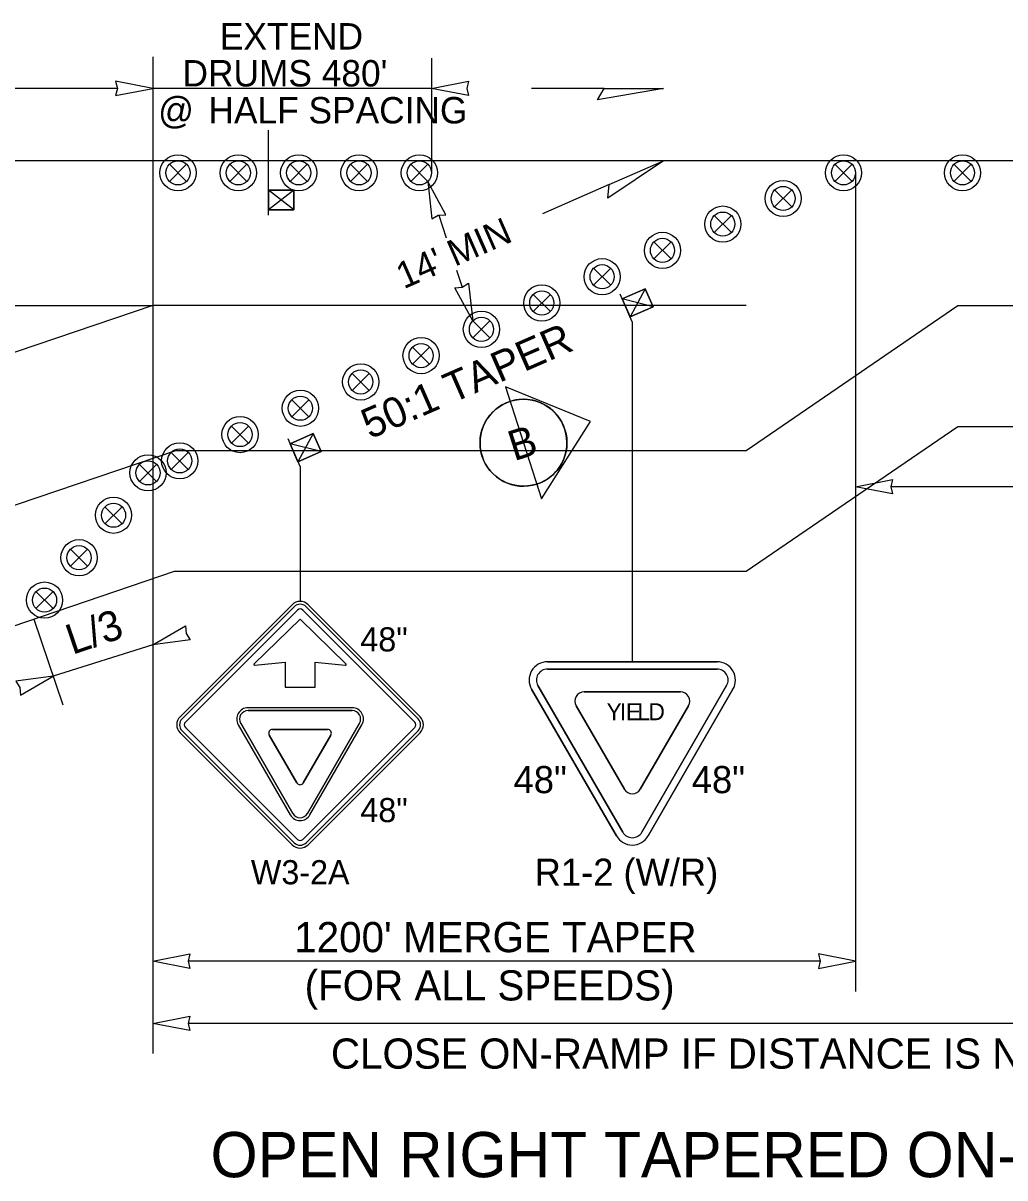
# Model space of a CAD drawing. Extents: x 99999 to 100116, y 99995 to 100013.
# Drawn here: x 100070.259 to 100072.862, y 100004.799 to 100007.86 of the extents above; entities that cross this region are included whole.
import ezdxf

# ---------------------------------------------------------------- set-up
doc = ezdxf.new("R2010")
doc.units = 0
for name, color, linetype in [('RD_MK_LineEdgeYellow', 7, 'Continuous'), ('RD_MK_LineLane', 7, 'Continuous'), ('SH_DE_DetailHeading2Text', 7, 'Continuous'), ('SH_GI_SectionCut', 7, 'Continuous'), ('TR_SN_ConstructionSigns', 7, 'Continuous'), ('TR_WZ_PortableSignMount5ftMinBlk-Org', 7, 'Continuous'), ('TR_WZ_PortableSignMount5ftMinRed-Wht', 7, 'Continuous'), ('TR_WZ_TrafficSafetyDrum', 7, 'Continuous'), ('TR_WZ_WorkZoneDetails', 7, 'Continuous'), ('TR_WZ_WorkZoneTextCurrent', 7, 'Continuous')]:
    doc.layers.add(name, color=color, linetype=linetype)

msp = doc.modelspace()

# ---------------------------------------------------------------- linework, layer by layer
at = {"layer": 'RD_MK_LineEdgeYellow'}
for p, q in [((100072.1758, 100006.7269), (100072.7368, 100007.1109)), ((100072.7368, 100007.1109), (100075.43, 100007.1109)), ((100070.6655, 100006.7269), (100068.195, 100005.8927)), ((100070.6655, 100006.7269), (100072.1758, 100006.7269))]:
    msp.add_line(p, q, dxfattribs=at)
at = {"layer": 'RD_MK_LineLane'}
for points in [[(100075.43, 100007.4949), (100068.195, 100007.4949)], [(100072.1758, 100007.1109), (100070.6024, 100007.1109)]]:
    msp.add_lwpolyline(points, dxfattribs=at)
at = {"layer": 'SH_GI_SectionCut'}
for p, q in [((100071.5379, 100006.8959), (100071.5503, 100006.8571)), ((100071.7627, 100006.8041), (100071.5379, 100006.8959)), ((100071.5379, 100006.8959), (100071.6329, 100006.5989)), ((100071.6329, 100006.5989), (100071.7627, 100006.8041)), ((100071.6205, 100006.6377), (100071.6329, 100006.5989))]:
    msp.add_line(p, q, dxfattribs=at)
msp.add_circle((100071.5854, 100006.7474), 0.1152, dxfattribs=at)
for start, end in [(17.7228, 287.7205), (287.7205, 107.725), (287.7205, 17.7228)]:
    msp.add_arc((100071.5854, 100006.7474), 0.1152, start, end, dxfattribs=at)
at = {"layer": 'TR_SN_ConstructionSigns'}
for p, q in [((100070.9719, 100006.3181), (100070.6749, 100006.0211)), ((100070.9772, 100006.3128), (100070.6802, 100006.0158)), ((100070.689, 100006.007), (100070.986, 100006.304)), ((100071.0002, 100006.304), (100071.2971, 100006.007)), ((100071.306, 100006.0158), (100071.009, 100006.3128)), ((100071.3113, 100006.0211), (100071.0143, 100006.3181)), ((100070.9931, 100006.2799), (100070.8713, 100006.1617)), ((100071.1148, 100006.1617), (100070.9931, 100006.2799)), ((100070.8733, 100006.1574), (100070.9531, 100006.1658)), ((100070.9531, 100006.1658), (100070.9531, 100006.0999)), ((100071.0331, 100006.0999), (100071.0331, 100006.1658)), ((100071.0331, 100006.1658), (100071.1128, 100006.1574)), ((100072.0987, 100006.1669), (100071.6491, 100006.1669)), ((100071.6491, 100006.1475), (100071.6491, 100006.1476)), ((100071.6491, 100006.1476), (100071.8739, 100006.1476)), ((100071.8739, 100006.1476), (100071.6491, 100006.1476)), ((100071.6491, 100006.1476), (100071.6491, 100006.1475)), ((100070.9531, 100006.0999), (100071.0331, 100006.0999)), ((100071.8317, 100005.7052), (100071.6069, 100006.0939)), ((100071.6069, 100006.0939), (100071.8317, 100005.7052)), ((100071.8486, 100005.715), (100071.6238, 100006.1036)), ((100071.6238, 100006.1036), (100071.8486, 100005.715)), ((100071.8739, 100006.0867), (100071.7461, 100006.0867)), ((100071.7461, 100006.0867), (100071.8739, 100006.0867)), ((100072.0017, 100006.0867), (100071.8739, 100006.0867)), ((100071.8739, 100006.0867), (100072.0017, 100006.0867)), ((100072.124, 100006.1036), (100071.8992, 100005.715)), ((100071.8992, 100005.715), (100072.124, 100006.1036)), ((100072.1408, 100006.0939), (100071.916, 100005.7052)), ((100071.916, 100005.7052), (100072.1408, 100006.0939)), ((100071.1311, 100006.0449), (100070.855, 100006.0449)), ((100070.855, 100006.0374), (100071.1311, 100006.0374)), ((100071.1311, 100006.0374), (100070.855, 100006.0374)), ((100071.725, 100006.0502), (100071.8528, 100005.8293)), ((100071.8528, 100005.8293), (100071.725, 100006.0502)), ((100071.895, 100005.8293), (100072.0228, 100006.0502)), ((100072.0228, 100006.0502), (100071.895, 100005.8293)), ((100070.986, 100005.6959), (100070.689, 100005.9929)), ((100070.8291, 100005.9999), (100070.9671, 100005.7608)), ((100070.9736, 100005.7646), (100070.8356, 100006.0037)), ((100070.8356, 100006.0037), (100070.9736, 100005.7646)), ((100071.2971, 100005.9929), (100071.0002, 100005.6959)), ((100071.1506, 100006.0037), (100071.0126, 100005.7646)), ((100071.0126, 100005.7646), (100071.1506, 100006.0037)), ((100071.0191, 100005.7608), (100071.1571, 100005.9999)), ((100070.6749, 100005.9787), (100070.9719, 100005.6817)), ((100070.6802, 100005.984), (100070.9772, 100005.687)), ((100070.9113, 100005.9724), (100070.9844, 100005.8458)), ((100070.9844, 100005.8458), (100070.9113, 100005.9724)), ((100071.0662, 100005.9874), (100070.92, 100005.9874)), ((100070.92, 100005.9874), (100071.0662, 100005.9874)), ((100071.0017, 100005.8458), (100071.0748, 100005.9724)), ((100071.0748, 100005.9724), (100071.0017, 100005.8458)), ((100071.009, 100005.687), (100071.306, 100005.984)), ((100071.0143, 100005.6817), (100071.3113, 100005.9787))]:
    msp.add_line(p, q, dxfattribs=at)
for points in [[(100071.6491, 100006.1669), (100072.0987, 100006.1669)], [(100071.8739, 100006.1476), (100072.0987, 100006.1476), (100072.0987, 100006.1475)], [(100072.0987, 100006.1475), (100072.0987, 100006.1476), (100071.8739, 100006.1476)]]:
    msp.add_lwpolyline(points, dxfattribs=at)
for centre, radius, start, end in [((100070.9931, 100006.2969), 0.03, 45, 135), ((100070.9931, 100006.2969), 0.0225, 45, 135), ((100070.9931, 100006.2969), 0.01, 45, 135), ((100070.8731, 100006.1599), 0.0025, 134.1559, 275.9533), ((100071.1131, 100006.1599), 0.0025, 264.0467, 45.8441), ((100071.6491, 100006.1182), 0.0487, 90, 210.0517), ((100071.6491, 100006.1182), 0.0487, 90, 210.0517), ((100071.6491, 100006.1182), 0.0292, 90, 210.0517), ((100071.6491, 100006.1182), 0.0292, 90, 210.0517), ((100072.0987, 100006.1182), 0.0487, 329.9522, 90), ((100072.0987, 100006.1182), 0.0487, 329.9522, 90), ((100072.0987, 100006.1182), 0.0292, 329.9522, 90), ((100072.0987, 100006.1182), 0.0292, 329.9522, 90), ((100071.7461, 100006.0624), 0.0244, 90, 210.0513), ((100071.7461, 100006.0624), 0.0244, 90, 210.0513), ((100072.0017, 100006.0624), 0.0244, 329.9514, 90), ((100072.0017, 100006.0624), 0.0244, 329.9514, 90), ((100070.6961, 100005.9999), 0.03, 135, 225), ((100070.855, 100006.0149), 0.03, 90, 210), ((100070.855, 100006.0149), 0.0225, 90, 210), ((100070.855, 100006.0149), 0.0225, 90, 210), ((100071.1311, 100006.0149), 0.03, 330, 90), ((100071.1311, 100006.0149), 0.0225, 330, 90), ((100071.1311, 100006.0149), 0.0225, 330, 90), ((100071.2901, 100005.9999), 0.03, 315, 45), ((100070.6961, 100005.9999), 0.0225, 135, 225), ((100070.6961, 100005.9999), 0.01, 135, 225), ((100071.2901, 100005.9999), 0.01, 315, 45), ((100071.2901, 100005.9999), 0.0225, 315, 45), ((100070.92, 100005.9774), 0.01, 90, 210), ((100070.92, 100005.9774), 0.01, 90, 210), ((100071.0662, 100005.9774), 0.01, 330, 90), ((100071.0662, 100005.9774), 0.01, 330, 90), ((100070.9931, 100005.8508), 0.01, 210, 330), ((100070.9931, 100005.8508), 0.01, 210, 330), ((100071.8739, 100005.8415), 0.0244, 210.0519, 329.9525), ((100071.8739, 100005.8415), 0.0244, 210.0519, 329.9525), ((100070.9931, 100005.7758), 0.03, 210, 330), ((100070.9931, 100005.7758), 0.0225, 210, 330), ((100070.9931, 100005.7758), 0.0225, 210, 330), ((100071.8739, 100005.7296), 0.0292, 210.0518, 329.9516), ((100071.8739, 100005.7296), 0.0292, 210.0518, 329.9516), ((100070.9931, 100005.7029), 0.0225, 225, 315), ((100070.9931, 100005.7029), 0.01, 225, 315), ((100071.8739, 100005.7296), 0.0487, 210.0518, 329.9516), ((100071.8739, 100005.7296), 0.0487, 210.0518, 329.9516), ((100070.9931, 100005.7029), 0.03, 225, 315)]:
    msp.add_arc(centre, radius, start, end, dxfattribs=at)
at = {"layer": 'TR_WZ_PortableSignMount5ftMinBlk-Org'}
for p, q in [((100070.9094, 100007.3509), (100070.9094, 100007.4309)), ((100070.9761, 100007.4169), (100070.9094, 100007.3649)), ((100070.9761, 100007.3649), (100070.9094, 100007.4169)), ((100070.9427, 100007.3909), (100070.9427, 100007.3909)), ((100070.9428, 100007.391), (100070.9428, 100007.391)), ((100070.9931, 100006.6844), (100070.9611, 100006.7577)), ((100071.0279, 100006.7715), (100070.9875, 100006.6972)), ((100071.0486, 100006.7239), (100070.9667, 100006.7449)), ((100071.0077, 100006.7344), (100071.0077, 100006.7344)), ((100071.0078, 100006.7345), (100071.0078, 100006.7345))]:
    msp.add_line(p, q, dxfattribs=at)
for points in [[(100070.9761, 100007.4169), (100070.9761, 100007.3649), (100070.9094, 100007.3649), (100070.9094, 100007.4169)], [(100070.9094, 100007.3649), (100070.9761, 100007.3649), (100070.9761, 100007.4169), (100070.9094, 100007.4169)], [(100071.0279, 100006.7715), (100071.0486, 100006.7239), (100070.9875, 100006.6972), (100070.9667, 100006.7449)], [(100070.9875, 100006.6972), (100071.0486, 100006.7239), (100071.0279, 100006.7715), (100070.9667, 100006.7449)]]:
    msp.add_lwpolyline(points, close=True, dxfattribs=at)
at = {"layer": 'TR_WZ_PortableSignMount5ftMinRed-Wht'}
for p, q in [((100071.9084, 100007.1554), (100071.868, 100007.0811)), ((100071.8736, 100007.0683), (100071.8416, 100007.1416)), ((100071.9291, 100007.1078), (100071.8472, 100007.1288)), ((100071.8882, 100007.1184), (100071.8882, 100007.1184)), ((100071.8882, 100007.1183), (100071.8882, 100007.1183))]:
    msp.add_line(p, q, dxfattribs=at)
for points in [[(100071.9084, 100007.1554), (100071.9291, 100007.1078), (100071.868, 100007.0811), (100071.8472, 100007.1288)], [(100071.868, 100007.0811), (100071.9291, 100007.1078), (100071.9084, 100007.1554), (100071.8472, 100007.1288)]]:
    msp.add_lwpolyline(points, close=True, dxfattribs=at)
at = {"layer": 'TR_WZ_TrafficSafetyDrum'}
for p, q in [((100070.6468, 100007.4855), (100070.692, 100007.4403)), ((100070.692, 100007.4855), (100070.6468, 100007.4403)), ((100070.8068, 100007.4855), (100070.852, 100007.4403)), ((100070.852, 100007.4855), (100070.8068, 100007.4403)), ((100070.9668, 100007.4855), (100071.012, 100007.4403)), ((100071.012, 100007.4855), (100070.9668, 100007.4403)), ((100071.1268, 100007.4855), (100071.172, 100007.4403)), ((100071.172, 100007.4855), (100071.1268, 100007.4403)), ((100071.2868, 100007.4855), (100071.332, 100007.4403)), ((100071.332, 100007.4855), (100071.2868, 100007.4403)), ((100072.4113, 100007.4855), (100072.4566, 100007.4403)), ((100072.4566, 100007.4855), (100072.4113, 100007.4403)), ((100072.7268, 100007.4855), (100072.772, 100007.4403)), ((100072.772, 100007.4855), (100072.7268, 100007.4403)), ((100072.2513, 100007.4176), (100072.2966, 100007.3724)), ((100072.2966, 100007.4176), (100072.2513, 100007.3724)), ((100072.0913, 100007.3497), (100072.1366, 100007.3045)), ((100072.1366, 100007.3497), (100072.0913, 100007.3045)), ((100071.9313, 100007.28), (100071.9766, 100007.2347)), ((100071.9766, 100007.28), (100071.9313, 100007.2347)), ((100071.7713, 100007.2102), (100071.8166, 100007.165)), ((100071.8166, 100007.2102), (100071.7713, 100007.165)), ((100071.6113, 100007.1405), (100071.6566, 100007.0952)), ((100071.6566, 100007.1405), (100071.6113, 100007.0952)), ((100071.4513, 100007.0708), (100071.4966, 100007.0255)), ((100071.4966, 100007.0708), (100071.4513, 100007.0255)), ((100071.2913, 100007.001), (100071.3366, 100006.9558)), ((100071.3366, 100007.001), (100071.2913, 100006.9558)), ((100071.1313, 100006.9313), (100071.1766, 100006.886)), ((100071.1766, 100006.9313), (100071.1313, 100006.886)), ((100070.9713, 100006.8615), (100071.0166, 100006.8163)), ((100071.0166, 100006.8615), (100070.9713, 100006.8163)), ((100070.8113, 100006.7918), (100070.8566, 100006.7465)), ((100070.8566, 100006.7918), (100070.8113, 100006.7465)), ((100070.6513, 100006.722), (100070.6966, 100006.6768)), ((100070.6966, 100006.722), (100070.6513, 100006.6768)), ((100070.5673, 100006.6902), (100070.6125, 100006.645)), ((100070.6125, 100006.6902), (100070.5673, 100006.645)), ((100070.4758, 100006.5778), (100070.5211, 100006.5325)), ((100070.5211, 100006.5778), (100070.4758, 100006.5325)), ((100070.3844, 100006.4653), (100070.4296, 100006.4201)), ((100070.4296, 100006.4653), (100070.3844, 100006.4201)), ((100070.2929, 100006.3529), (100070.3382, 100006.3076)), ((100070.3382, 100006.3529), (100070.2929, 100006.3076))]:
    msp.add_line(p, q, dxfattribs=at)
for centre, radius in [((100070.6694, 100007.4629), 0.048), ((100070.6694, 100007.4629), 0.048), ((100070.6694, 100007.4629), 0.032), ((100070.8294, 100007.4629), 0.048), ((100070.8294, 100007.4629), 0.048), ((100070.8294, 100007.4629), 0.032), ((100070.9894, 100007.4629), 0.048), ((100070.9894, 100007.4629), 0.048), ((100070.9894, 100007.4629), 0.032), ((100071.1494, 100007.4629), 0.048), ((100071.1494, 100007.4629), 0.048), ((100071.1494, 100007.4629), 0.032), ((100071.3094, 100007.4629), 0.048), ((100071.3094, 100007.4629), 0.048), ((100071.3094, 100007.4629), 0.032), ((100072.4339, 100007.4629), 0.048), ((100072.4339, 100007.4629), 0.048), ((100072.4339, 100007.4629), 0.032), ((100072.7494, 100007.4629), 0.048), ((100072.7494, 100007.4629), 0.048), ((100072.7494, 100007.4629), 0.032), ((100072.2739, 100007.395), 0.048), ((100072.2739, 100007.395), 0.048), ((100072.2739, 100007.395), 0.032), ((100072.1139, 100007.3271), 0.048), ((100072.1139, 100007.3271), 0.048), ((100072.1139, 100007.3271), 0.032), ((100071.9539, 100007.2574), 0.048), ((100071.9539, 100007.2574), 0.048), ((100071.9539, 100007.2574), 0.032), ((100071.7939, 100007.1876), 0.048), ((100071.7939, 100007.1876), 0.048), ((100071.7939, 100007.1876), 0.032), ((100071.6339, 100007.1179), 0.048), ((100071.6339, 100007.1179), 0.048), ((100071.6339, 100007.1179), 0.032), ((100071.4739, 100007.0481), 0.048), ((100071.4739, 100007.0481), 0.048), ((100071.4739, 100007.0481), 0.032), ((100071.3139, 100006.9784), 0.048), ((100071.3139, 100006.9784), 0.048), ((100071.3139, 100006.9784), 0.032), ((100071.1539, 100006.9086), 0.048), ((100071.1539, 100006.9086), 0.048), ((100071.1539, 100006.9086), 0.032), ((100070.9939, 100006.8389), 0.048), ((100070.9939, 100006.8389), 0.048), ((100070.9939, 100006.8389), 0.032), ((100070.8339, 100006.7691), 0.048), ((100070.8339, 100006.7691), 0.048), ((100070.8339, 100006.7691), 0.032), ((100070.6739, 100006.6994), 0.048), ((100070.6739, 100006.6994), 0.048), ((100070.6739, 100006.6994), 0.032), ((100070.5899, 100006.6676), 0.048), ((100070.5899, 100006.6676), 0.048), ((100070.5899, 100006.6676), 0.032), ((100070.4985, 100006.5552), 0.048), ((100070.4985, 100006.5552), 0.048), ((100070.4985, 100006.5552), 0.032), ((100070.407, 100006.4427), 0.048), ((100070.407, 100006.4427), 0.048), ((100070.407, 100006.4427), 0.032), ((100070.3156, 100006.3303), 0.048), ((100070.3156, 100006.3303), 0.048), ((100070.3156, 100006.3303), 0.032)]:
    msp.add_circle(centre, radius, dxfattribs=at)
at = {"layer": 'TR_WZ_WorkZoneDetails'}
for p, q in [((100070.6024, 100007.7703), (100070.6024, 100005.1282)), ((100071.3414, 100007.7669), (100071.3414, 100007.4629)), ((100070.5087, 100007.6869), (100068.2887, 100007.6869)), ((100071.3414, 100007.6869), (100070.6024, 100007.6869)), ((100071.7994, 100007.6869), (100071.6065, 100007.6869)), ((100070.9094, 100007.4309), (100070.9094, 100007.5759)), ((100072.4659, 100007.4629), (100072.4659, 100005.2929)), ((100071.8126, 100007.4317), (100071.6361, 100007.354)), ((100071.3609, 100007.3508), (100071.3803, 100007.2908)), ((100071.408, 100007.2047), (100071.4225, 100007.1599)), ((100069.2533, 100007.1109), (100070.6024, 100007.1109)), ((100070.6024, 100007.1109), (100069.2943, 100006.6692)), ((100071.8736, 100007.0683), (100071.8739, 100006.1669)), ((100072.1758, 100006.4069), (100072.7368, 100006.7909)), ((100072.7368, 100006.7909), (100075.43, 100006.7909)), ((100070.9931, 100006.6844), (100070.9931, 100006.3269)), ((100073.599, 100006.6309), (100072.5596, 100006.6309)), ((100068.195, 100005.5689), (100070.6601, 100006.4069)), ((100070.6601, 100006.4069), (100072.1758, 100006.4069)), ((100070.2871, 100006.2801), (100070.3643, 100006.0529)), ((100070.6024, 100006.2119), (100070.3386, 100006.1286)), ((100072.3722, 100005.3729), (100070.6962, 100005.3729)), ((100074.3691, 100005.2082), (100070.6962, 100005.2082))]:
    msp.add_line(p, q, dxfattribs=at)
for points in [[(100070.6024, 100007.6869), (100070.5041, 100007.7062), (100070.5087, 100007.6869), (100070.5041, 100007.6676)], [(100071.3414, 100007.6869), (100071.4396, 100007.7062), (100071.4351, 100007.6869), (100071.4396, 100007.6676)], [(100071.9566, 100007.6869), (100071.7815, 100007.6561), (100071.7994, 100007.6869)], [(100071.9566, 100007.4949), (100071.8087, 100007.3962), (100071.8126, 100007.4317)], [(100071.332, 100007.4403), (100071.3424, 100007.3407), (100071.3595, 100007.3507), (100071.3792, 100007.352)], [(100071.4513, 100007.0708), (100071.403, 100007.1585), (100071.4227, 100007.16), (100071.4397, 100007.1702)], [(100072.4659, 100006.6309), (100072.5642, 100006.6502), (100072.5596, 100006.6309), (100072.5642, 100006.6116)], [(100070.6024, 100006.2119), (100070.6893, 100006.2618), (100070.6912, 100006.2421), (100070.7017, 100006.2253)], [(100070.3386, 100006.1286), (100070.2393, 100006.1152), (100070.2498, 100006.0985), (100070.2517, 100006.0787)], [(100070.6024, 100005.3729), (100070.7007, 100005.3922), (100070.6962, 100005.3729), (100070.7007, 100005.3537)], [(100072.4659, 100005.3729), (100072.3676, 100005.3922), (100072.3722, 100005.3729), (100072.3676, 100005.3537)], [(100070.6024, 100005.2082), (100070.7007, 100005.2275), (100070.6962, 100005.2082), (100070.7007, 100005.1889)]]:
    msp.add_lwpolyline(points, close=True, dxfattribs=at)

# ---------------------------------------------------------------- texts
at = {"layer": 'SH_DE_DetailHeading2Text'}
msp.add_text('OPEN RIGHT TAPERED ON-RAMP DETAIL', height=0.12, rotation=360, dxfattribs=at).set_placement((100070.7557, 100004.8003))
at = {"layer": 'SH_GI_SectionCut'}
msp.add_text('B', height=0.08, rotation=17.7128, dxfattribs=at).set_placement((100071.5605, 100006.6982))
at = {"layer": 'TR_SN_ConstructionSigns'}
for s, height, p in [('48"', 0.064, (100071.1529, 100006.1942)), ('48"', 0.072, (100072.0316, 100005.8185)), ('48"', 0.064, (100071.1529, 100005.7416)), ('W3-2A', 0.064, (100070.8627, 100005.5769)), ('R1-2 (W/R)', 0.072, (100071.6151, 100005.5729))]:
    msp.add_text(s, height=height, rotation=360, dxfattribs=at).set_placement(p)
for s, height, p in [('Y', 0.045, (100071.8057, 100006.0119)), ('I', 0.045, (100071.8408, 100006.0119)), ('E', 0.045, (100071.857, 100006.0119)), ('L', 0.045, (100071.8876, 100006.0119)), ('D', 0.045, (100071.9168, 100006.0119)), ('48"', 0.072, (100071.5592, 100005.8185))]:
    msp.add_text(s, height=height, dxfattribs=at).set_placement(p)
at = {"layer": 'TR_WZ_WorkZoneTextCurrent'}
for s, height, p in [('EXTEND', 0.07, (100070.7804, 100007.7899)), ("DRUMS 480'", 0.07, (100070.6813, 100007.6919)), ('@', 0.07, (100070.6167, 100007.5939)), ('HALF SPACING', 0.07, (100070.7502, 100007.5939)), ("1200' MERGE TAPER", 0.08, (100070.9776, 100005.3969)), ('(FOR ALL SPEEDS)', 0.08, (100071.0051, 100005.2689)), ('CLOSE ON-RAMP IF DISTANCE IS NOT AVAILABLE', 0.08, (100071.0749, 100005.0882))]:
    msp.add_text(s, height=height, dxfattribs=at).set_placement(p)
for s, height, rotation, p in [("14' MIN", 0.07, 23.7238, (100071.2678, 100007.154)), ('50:1 TAPER', 0.08, 23.5731, (100071.178, 100006.7561)), ('L/3', 0.08, 18.775, (100070.3892, 100006.1849))]:
    msp.add_text(s, height=height, rotation=rotation, dxfattribs=at).set_placement(p)

doc.saveas('drawing.dxf')
